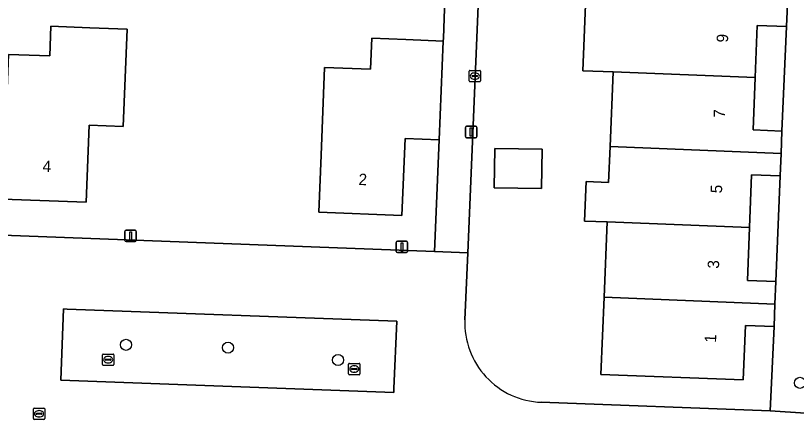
# Model space of a CAD drawing. Extents: x 160786 to 161429, y 386828 to 387485.
# Drawn here: x 160910.9 to 160979.3, y 386926.7 to 386962.8 of the extents above; entities that cross this region are included whole.
import ezdxf

# ---------------------------------------------------------------- set-up
doc = ezdxf.new("R2010")
doc.units = 0
for name, color, linetype in [('IMGEO_Boom', 7, 'Continuous'), ('IMGEO_Erf', 7, 'Continuous'), ('IMGEO_Kolk', 7, 'Continuous'), ('IMGEO_Lichtmast', 7, 'Continuous'), ('IMGEO_Pand', 7, 'Continuous'), ('IMGEO_Pand_nummerreeks', 7, 'Continuous'), ('IMGEO_Parkeervlak_open', 7, 'Continuous'), ('IMGEO_Rijbaan_lokaal_open', 7, 'Continuous'), ('IMGEO_Rioolput', 7, 'Continuous'), ('IMGEO_Voetpad_open', 7, 'Continuous')]:
    doc.layers.add(name, color=color, linetype=linetype)

msp = doc.modelspace()

# ---------------------------------------------------------------- linework, layer by layer
at = {"layer": 'IMGEO_Boom'}
for centre in [(160920.55, 386933.892), (160929.487, 386933.645), (160939.132, 386932.56), (160979.614, 386930.557)]:
    msp.add_circle(centre, 0.489, dxfattribs=at)
at = {"layer": 'IMGEO_Erf'}
for points in [[(160963.237, 386957.833), (160960.572, 386957.94), (160960.835, 386964.479), (160960.588, 386964.489), (160960.853, 386971.08), (160963.765, 386970.963), (160964.033, 386977.609), (160964.298, 386984.198), (160961.465, 386984.306), (160958.409, 386984.422), (160955.353, 386984.539), (160952.296, 386984.655), (160950.494, 386941.959), (160950.247, 386936.098)], [(160909.763, 386943.521), (160947.593, 386942.07), (160948.003, 386951.885), (160945.006, 386952.006), (160944.734, 386945.242), (160937.44, 386945.536), (160937.641, 386950.532), (160937.951, 386958.226), (160941.986, 386958.064), (160942.096, 386960.786), (160945.075, 386960.666), (160948.351, 386960.534), (160948.361, 386960.785), (160948.785, 386972.899)], [(160956.943, 386928.854), (160977.011, 386928.093), (160977.347, 386935.491), (160974.83, 386935.586), (160974.649, 386930.813), (160962.169, 386931.288), (160962.442, 386938.071), (160962.708, 386944.674), (160960.743, 386944.753), (160960.882, 386948.222), (160962.847, 386948.143), (160962.973, 386951.283), (160963.237, 386957.833)]]:
    msp.add_lwpolyline(points, dxfattribs=at)
for points in [[(160920.31, 386953.033), (160917.312, 386953.151), (160917.047, 386946.397), (160909.753, 386946.684), (160910.252, 386959.376), (160913.869, 386959.233), (160913.972, 386961.847), (160917.38, 386961.713), (160920.647, 386961.585)], [(160978.441, 386961.82), (160975.868, 386961.918), (160975.694, 386957.332), (160975.519, 386952.745), (160978.026, 386952.65)], [(160957.012, 386951.069), (160956.971, 386947.615), (160952.819, 386947.664), (160952.86, 386951.118)], [(160977.876, 386948.712), (160975.364, 386948.807), (160975.187, 386944.172), (160975.011, 386939.541), (160977.497, 386939.446)]]:
    msp.add_lwpolyline(points, close=True, dxfattribs=at)
msp.add_arc((160957.207, 386935.814), 6.965, 177.66597, 267.8316, dxfattribs=at)
at = {"layer": 'IMGEO_Kolk'}
for p, q in [((160950.693, 386957.969), (160951.545, 386957.969)), ((160950.618, 386957.043), (160950.618, 386957.895)), ((160950.877, 386957.463), (160950.877, 386957.475)), ((160951.315, 386957.426), (160950.917, 386957.426)), ((160950.92, 386957.512), (160951.318, 386957.512)), ((160951.106, 386957.749), (160951.131, 386957.749)), ((160951.361, 386957.475), (160951.361, 386957.463)), ((160951.619, 386957.895), (160951.619, 386957.043)), ((160951.545, 386956.969), (160950.693, 386956.969)), ((160951.129, 386957.189), (160951.104, 386957.189)), ((160918.486, 386932.161), (160918.486, 386933.013)), ((160918.561, 386933.087), (160919.413, 386933.087)), ((160918.745, 386932.581), (160918.745, 386932.593)), ((160918.788, 386932.63), (160919.186, 386932.63)), ((160918.974, 386932.867), (160918.999, 386932.867)), ((160919.229, 386932.593), (160919.229, 386932.581)), ((160919.487, 386933.013), (160919.487, 386932.161)), ((160919.413, 386932.087), (160918.561, 386932.087)), ((160919.183, 386932.544), (160918.785, 386932.544)), ((160918.997, 386932.307), (160918.972, 386932.307)), ((160940.053, 386931.342), (160940.053, 386932.194)), ((160940.128, 386932.268), (160940.98, 386932.268)), ((160940.541, 386932.048), (160940.566, 386932.048)), ((160941.054, 386932.194), (160941.054, 386931.342)), ((160940.98, 386931.268), (160940.128, 386931.268)), ((160940.312, 386931.762), (160940.312, 386931.774)), ((160940.75, 386931.725), (160940.352, 386931.725)), ((160940.355, 386931.811), (160940.753, 386931.811)), ((160940.564, 386931.488), (160940.539, 386931.488)), ((160940.796, 386931.774), (160940.796, 386931.762))]:
    msp.add_line(p, q, dxfattribs=at)
for points in [[(160950.693, 386957.969), (160951.545, 386957.969)], [(160950.618, 386957.043), (160950.618, 386957.895)], [(160951.619, 386957.895), (160951.619, 386957.043)], [(160951.545, 386956.969), (160950.693, 386956.969)], [(160918.486, 386932.161), (160918.486, 386933.013)], [(160918.561, 386933.087), (160919.413, 386933.087)], [(160919.487, 386933.013), (160919.487, 386932.161)], [(160919.413, 386932.087), (160918.561, 386932.087)], [(160940.053, 386931.342), (160940.053, 386932.194)], [(160940.128, 386932.268), (160940.98, 386932.268)], [(160941.054, 386932.194), (160941.054, 386931.342)], [(160940.98, 386931.268), (160940.128, 386931.268)]]:
    msp.add_lwpolyline(points, dxfattribs=at)
for centre, radius, start, end in [((160950.695, 386957.893), 0.0765, 91.55205, 178.44795), ((160950.695, 386957.893), 0.0765, 91.55205, 178.44795), ((160951.543, 386957.893), 0.0765, 1.55205, 88.44795), ((160951.543, 386957.893), 0.0765, 1.55205, 88.44795), ((160950.917, 386957.472), 0.0403, 85.87752, 175.75265), ((160950.914, 386957.462), 0.0366, 178.93798, 274.71019), ((160951.318, 386957.469), 0.043, 264.86636, 352.45326), ((160951.322, 386957.474), 0.0386, 1.73085, 96.63898), ((160950.695, 386957.045), 0.0765, 181.55205, 268.44795), ((160950.695, 386957.045), 0.0765, 181.55205, 268.44795), ((160951.543, 386957.045), 0.0765, 271.55205, 358.44795), ((160951.543, 386957.045), 0.0765, 271.55205, 358.44795), ((160918.563, 386933.011), 0.0765, 91.55205, 178.44795), ((160918.563, 386933.011), 0.0765, 91.55205, 178.44795), ((160918.785, 386932.59), 0.0403, 85.87752, 175.75265), ((160919.19, 386932.592), 0.0386, 1.73085, 96.63898), ((160919.411, 386933.011), 0.0765, 1.55205, 88.44795), ((160919.411, 386933.011), 0.0765, 1.55205, 88.44795), ((160918.563, 386932.163), 0.0765, 181.55205, 268.44795), ((160918.563, 386932.163), 0.0765, 181.55205, 268.44795), ((160918.782, 386932.58), 0.0366, 178.93798, 274.71019), ((160919.186, 386932.587), 0.043, 264.86636, 352.45326), ((160919.411, 386932.163), 0.0765, 271.55205, 358.44795), ((160919.411, 386932.163), 0.0765, 271.55205, 358.44795), ((160940.13, 386932.192), 0.0765, 91.55205, 178.44795), ((160940.13, 386932.192), 0.0765, 91.55205, 178.44795), ((160940.978, 386932.192), 0.0765, 1.55205, 88.44795), ((160940.978, 386932.192), 0.0765, 1.55205, 88.44795), ((160940.13, 386931.344), 0.0765, 181.55205, 268.44795), ((160940.13, 386931.344), 0.0765, 181.55205, 268.44795), ((160940.352, 386931.771), 0.0403, 85.87752, 175.75265), ((160940.349, 386931.761), 0.0366, 178.93798, 274.71019), ((160940.753, 386931.768), 0.043, 264.86636, 352.45326), ((160940.757, 386931.773), 0.0386, 1.73085, 96.63898), ((160940.978, 386931.344), 0.0765, 271.55205, 358.44795), ((160940.978, 386931.344), 0.0765, 271.55205, 358.44795)]:
    msp.add_arc(centre, radius, start, end, dxfattribs=at)
for centre, major_axis, ratio, start_param, end_param in [((160951.105, 386957.469), (-0.387, 0.002), 0.722429, 4.712389, 7.853982), ((160951.13, 386957.469), (-0.39, 0.002), 0.717154, 1.570796, 4.712389), ((160918.973, 386932.587), (-0.387, 0.002), 0.722429, 4.712389, 7.853982), ((160918.998, 386932.587), (-0.39, 0.002), 0.717154, 1.570796, 4.712389), ((160940.54, 386931.768), (-0.387, 0.002), 0.722429, 4.712389, 7.853982), ((160940.565, 386931.768), (-0.39, 0.002), 0.717154, 1.570796, 4.712389)]:
    msp.add_ellipse(centre, major_axis=major_axis, ratio=ratio, start_param=start_param, end_param=end_param, dxfattribs=at)
at = {"layer": 'IMGEO_Lichtmast'}
for p, q in [((160950.3, 386952.164), (160950.3, 386952.964)), ((160950.3, 386952.964), (160950.3, 386952.164)), ((160950.4, 386953.064), (160951.19, 386953.064)), ((160951.19, 386953.064), (160950.4, 386953.064)), ((160951.29, 386952.964), (160951.29, 386952.164)), ((160951.29, 386952.164), (160951.29, 386952.964)), ((160951.19, 386952.064), (160950.4, 386952.064)), ((160950.4, 386952.064), (160951.19, 386952.064)), ((160920.456, 386943.043), (160920.456, 386943.843)), ((160920.456, 386943.843), (160920.456, 386943.043)), ((160920.556, 386943.943), (160921.346, 386943.943)), ((160921.346, 386943.943), (160920.556, 386943.943)), ((160921.446, 386943.843), (160921.446, 386943.043)), ((160921.446, 386943.043), (160921.446, 386943.843)), ((160921.346, 386942.943), (160920.556, 386942.943)), ((160920.556, 386942.943), (160921.346, 386942.943)), ((160944.232, 386942.079), (160944.232, 386942.879)), ((160944.232, 386942.879), (160944.232, 386942.079)), ((160944.332, 386942.979), (160945.122, 386942.979)), ((160945.122, 386942.979), (160944.332, 386942.979)), ((160945.222, 386942.879), (160945.222, 386942.079)), ((160945.222, 386942.079), (160945.222, 386942.879)), ((160945.122, 386941.979), (160944.332, 386941.979)), ((160944.332, 386941.979), (160945.122, 386941.979))]:
    msp.add_line(p, q, dxfattribs=at)
for points in [[(160950.72, 386952.939), (160950.87, 386952.939), (160950.87, 386952.189), (160950.72, 386952.189), (160950.72, 386952.939)], [(160920.876, 386943.818), (160921.026, 386943.818), (160921.026, 386943.068), (160920.876, 386943.068), (160920.876, 386943.818)], [(160944.652, 386942.854), (160944.802, 386942.854), (160944.802, 386942.104), (160944.652, 386942.104), (160944.652, 386942.854)]]:
    msp.add_lwpolyline(points, dxfattribs=at)
for centre, start, end in [((160950.4, 386952.964), 90, 180), ((160950.4, 386952.964), 90, 180), ((160951.19, 386952.964), 0, 90), ((160951.19, 386952.964), 360, 90), ((160950.4, 386952.164), 180, 270), ((160950.4, 386952.164), 180, 270), ((160951.19, 386952.164), 270, 0), ((160951.19, 386952.164), 270, 0), ((160920.556, 386943.843), 90, 180), ((160920.556, 386943.843), 90, 180), ((160921.346, 386943.843), 0, 90), ((160921.346, 386943.843), 360, 90), ((160920.556, 386943.043), 180, 270), ((160920.556, 386943.043), 180, 270), ((160921.346, 386943.043), 270, 0), ((160921.346, 386943.043), 270, 0), ((160944.332, 386942.879), 90, 180), ((160944.332, 386942.879), 90, 180), ((160945.122, 386942.879), 0, 90), ((160945.122, 386942.879), 360, 90), ((160944.332, 386942.079), 180, 270), ((160944.332, 386942.079), 180, 270), ((160945.122, 386942.079), 270, 0), ((160945.122, 386942.079), 270, 0)]:
    msp.add_arc(centre, 0.1, start, end, dxfattribs=at)
at = {"layer": 'IMGEO_Pand'}
for points in [[(160978.516, 386963.768), (160963.5, 386964.372), (160960.835, 386964.479), (160960.572, 386957.94), (160963.237, 386957.833), (160975.694, 386957.332), (160975.868, 386961.918), (160978.441, 386961.82)], [(160910.252, 386959.376), (160909.753, 386946.684), (160917.047, 386946.397), (160917.312, 386953.151), (160920.31, 386953.033), (160920.647, 386961.585), (160917.38, 386961.713), (160913.972, 386961.847), (160913.869, 386959.233)], [(160948.351, 386960.534), (160945.075, 386960.666), (160942.096, 386960.786), (160941.986, 386958.064), (160937.951, 386958.226), (160937.641, 386950.532), (160937.44, 386945.536), (160944.734, 386945.242), (160945.006, 386952.006), (160948.003, 386951.885)], [(160978.026, 386952.65), (160975.519, 386952.745), (160975.694, 386957.332), (160963.237, 386957.833), (160962.973, 386951.283), (160977.951, 386950.68)], [(160952.819, 386947.664), (160956.971, 386947.615), (160957.012, 386951.069), (160952.86, 386951.118)], [(160975.364, 386948.807), (160977.876, 386948.712), (160977.951, 386950.68), (160962.973, 386951.283), (160962.847, 386948.143), (160960.882, 386948.222), (160960.743, 386944.753), (160962.708, 386944.674), (160975.187, 386944.172)], [(160977.497, 386939.446), (160975.011, 386939.541), (160975.187, 386944.172), (160962.708, 386944.674), (160962.442, 386938.071), (160977.422, 386937.468)], [(160977.422, 386937.468), (160962.442, 386938.071), (160962.169, 386931.288), (160974.649, 386930.813), (160974.83, 386935.586), (160977.347, 386935.491)]]:
    msp.add_lwpolyline(points, close=True, dxfattribs=at)
at = {"layer": 'IMGEO_Parkeervlak_open'}
msp.add_lwpolyline([(160944.275, 386935.956), (160915.395, 386937.025), (160915.058, 386937.038), (160914.826, 386930.792), (160944.009, 386929.711), (160944.024, 386930.071)], close=True, dxfattribs=at)
at = {"layer": 'IMGEO_Rijbaan_lokaal_open'}
msp.add_lwpolyline([(160950.247, 386936.098), (160950.494, 386941.959), (160947.593, 386942.07), (160909.763, 386943.521), (160909.024, 386925.361), (160908.899, 386922.288), (160924.183, 386921.716), (160939.56, 386921.141), (160942.121, 386921.036), (160965.405, 386920.165), (160967.922, 386920.071), (160968.031, 386922.765), (160970.467, 386922.647), (160978.3, 386922.336), (160979.942, 386922.265), (160980.09, 386927.898), (160977.011, 386928.093), (160956.943, 386928.854)], dxfattribs=at)
msp.add_lwpolyline([(160944.024, 386930.071), (160944.009, 386929.711), (160914.826, 386930.792), (160915.058, 386937.038), (160915.395, 386937.025), (160944.275, 386935.956)], close=True, dxfattribs=at)
msp.add_arc((160957.207, 386935.814), 6.965, 177.66597, 267.8316, dxfattribs=at)
at = {"layer": 'IMGEO_Rioolput'}
for p, q in [((160912.427, 386927.416), (160912.427, 386928.268)), ((160912.502, 386928.342), (160913.354, 386928.342)), ((160912.686, 386927.836), (160912.686, 386927.848)), ((160912.729, 386927.885), (160913.127, 386927.885)), ((160912.915, 386928.122), (160912.94, 386928.122)), ((160913.17, 386927.848), (160913.17, 386927.836)), ((160913.428, 386928.268), (160913.428, 386927.416)), ((160913.354, 386927.342), (160912.502, 386927.342)), ((160913.124, 386927.799), (160912.726, 386927.799)), ((160912.938, 386927.562), (160912.913, 386927.562))]:
    msp.add_line(p, q, dxfattribs=at)
for points in [[(160912.427, 386927.416), (160912.427, 386928.268)], [(160912.502, 386928.342), (160913.354, 386928.342)], [(160913.428, 386928.268), (160913.428, 386927.416)], [(160913.354, 386927.342), (160912.502, 386927.342)]]:
    msp.add_lwpolyline(points, dxfattribs=at)
for centre, radius, start, end in [((160912.504, 386928.266), 0.0765, 91.55205, 178.44795), ((160912.504, 386928.266), 0.0765, 91.55205, 178.44795), ((160912.726, 386927.845), 0.0403, 85.87752, 175.75265), ((160912.723, 386927.835), 0.0366, 178.93798, 274.71019), ((160913.127, 386927.842), 0.043, 264.86636, 352.45326), ((160913.131, 386927.847), 0.0386, 1.73085, 96.63898), ((160913.352, 386928.266), 0.0765, 1.55205, 88.44795), ((160913.352, 386928.266), 0.0765, 1.55205, 88.44795), ((160912.504, 386927.418), 0.0765, 181.55205, 268.44795), ((160912.504, 386927.418), 0.0765, 181.55205, 268.44795), ((160913.352, 386927.418), 0.0765, 271.55205, 358.44795), ((160913.352, 386927.418), 0.0765, 271.55205, 358.44795)]:
    msp.add_arc(centre, radius, start, end, dxfattribs=at)
for centre, major_axis, ratio, start_param, end_param in [((160912.914, 386927.842), (-0.387, 0.002), 0.722429, 4.712389, 7.853982), ((160912.939, 386927.842), (-0.39, 0.002), 0.717154, 1.570796, 4.712389)]:
    msp.add_ellipse(centre, major_axis=major_axis, ratio=ratio, start_param=start_param, end_param=end_param, dxfattribs=at)
at = {"layer": 'IMGEO_Voetpad_open'}
msp.add_lwpolyline([(160977.018, 386992.268), (160976.973, 386989.708), (160979.245, 386983.695), (160979.111, 386978.996), (160979.035, 386977.005), (160978.96, 386975.016), (160978.59, 386965.715), (160978.516, 386963.768), (160978.441, 386961.82), (160978.026, 386952.65), (160977.951, 386950.68), (160977.876, 386948.712), (160977.497, 386939.446), (160977.422, 386937.468), (160977.347, 386935.491), (160977.011, 386928.093), (160980.09, 386927.898), (160980.175, 386929.863), (160980.231, 386931.159), (160981.158, 386952.537), (160981.17, 386953.623), (160981.517, 386954.306), (160982.678, 386955.399)], dxfattribs=at)
msp.add_lwpolyline([(160952.296, 386984.655), (160952.524, 386990.638), (160949.494, 386990.753), (160949.354, 386986.945), (160949.245, 386983.983), (160949.046, 386978.827), (160948.785, 386972.899), (160948.361, 386960.785), (160948.351, 386960.534), (160948.003, 386951.885), (160947.593, 386942.07), (160950.494, 386941.959)], close=True, dxfattribs=at)

# ---------------------------------------------------------------- texts
at = {"layer": 'IMGEO_Pand_nummerreeks'}
for s, rotation, p in [('9', 87.72954, (160973.3, 386960.403)), ('7', 87.72954, (160973.038, 386953.789)), ('4', 357.74828, (160913.223, 386949.068)), ('2', 357.69098, (160940.912, 386947.919)), ('5', 87.7313, (160972.776, 386947.173)), ('3', 87.72954, (160972.514, 386940.56)), ('1', 87.72954, (160972.255, 386934.059))]:
    msp.add_text(s, height=1, rotation=rotation, dxfattribs=at).set_placement(p)

doc.saveas('drawing.dxf')
